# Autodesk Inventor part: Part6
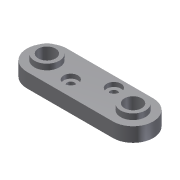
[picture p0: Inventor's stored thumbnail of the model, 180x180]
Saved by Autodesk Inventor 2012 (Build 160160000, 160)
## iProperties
Shininess: 77.0
Length Units: 11269
Angle Units: 11279
Time Units: 11290
Mass Units: 11283
Length Display Precision: 3
Angle Display Precision: 2
Created: 2002-01
Part Number: Part6
Document SubType Name: Modeling
Designer: ***
Density: 1 g/cm^3
Mass: 21.6911 g
Surface Area: 77.1136 cm^2
Volume: 21.6911 cm^3
Material: Default
Density: 0.0
Volumn: 0.0
Area: 0.0
PropertySet Name: Model Information
Control State: 0
Master: False
Checked Out: False
Author: ***
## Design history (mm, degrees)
sketch "Sketch1"
  geometry: L1 (-33.118, 12.346)-(26.882, 12.361); L2 (-33.111, -15.654)-(26.889, -15.639); C1 r 6 at (-33.114, -1.654); C2 r 6 at (26.886, -1.639); A1 r 14 centre (-33.114, -1.654) between (-33.118, 12.346) and (-33.111, -15.654); A2 r 14 centre (26.886, -1.639) between (26.889, -15.639) and (26.882, 12.361)
  constraints: 4 centre point, 4 end point, 4 point on circle, 4 tangent, 2 coincident, 2 equal radius
  dimensions: "d0" = 60 distance of L1.start L1.end; "d1" = 14 radius of A1; "d2" = 12 diameter of C1
extrude "Extrusion1" new body sketch "Sketch1" distance "d3" = 10; taper "d4" = 0 deg
sketch "Sketch2"
  geometry: C1 r 6 at (26.886, -1.639) reference; C2 r 6 at (-33.114, -1.654) reference; C3 r 8.694 at (-33.114, -1.654); C4 r 8.694 at (26.886, -1.639)
  constraints: 2 centre point, 2 coincident, 1 equal radius
extrude "Extrusion2" join sketch "Sketch2" distance "d5" = 4; taper "d6" = 0 deg
sketch "Sketch3"
  geometry: C1 r 8.694 at (-33.114, -1.654) reference; C2 r 8.694 at (26.886, -1.639) reference; 3 further points
  dimensions: "d7" = 20 horizontal distance of C1.centre point (-13.114, -5); "d8" = 20 horizontal distance of C2.centre point (6.886, 5); "d9" = 5 vertical distance of point (0, 0) point (6.886, 5); "d10" = 5 vertical distance of point (-13.114, -5) point (0, 0)
hole "Hole1" sketch "Sketch3" at (-13.114, -5), (6.886, 5) diameter "d11" = 5; stored, may be unused: countersink angle "d15" = 90 deg, drill point angle "d17" = 0 deg; dims "d12" = 6, "d13" = 10, "d14" = 3, "d16" = 8
body "Solid1"
